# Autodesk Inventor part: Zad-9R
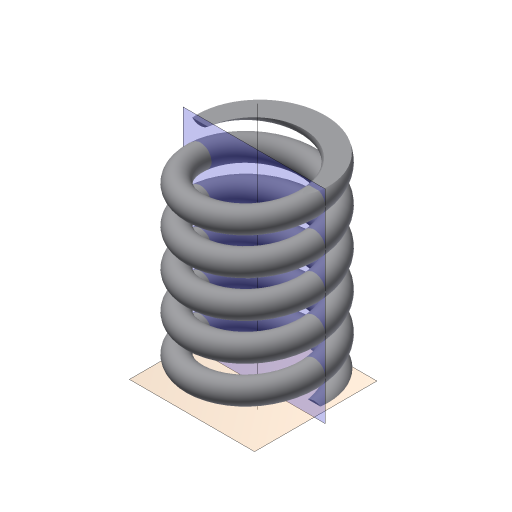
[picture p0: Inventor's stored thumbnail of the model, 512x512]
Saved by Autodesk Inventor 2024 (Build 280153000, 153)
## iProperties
Company: ATC
Shininess: 20.0
Length Units: 11269
Angle Units: 11279
Time Units: 11290
Mass Units: 11283
Length Display Precision: 3
Angle Display Precision: 2
Compacted: True
Created: 2023-03
Part Number: Zad-9R
Document SubType Name: Modeling
Designer: Andrzej Jaskulski
Density: 1 g/cm^3
Material: Default
Appearance: Domyślne
Checked By: A.J.
Engr Approved By: Andrzej Jaskulski
Mfg Approved By: Andrzej Jaskulski
Authority: A.J.
Density: 0.0
Volumn: 0.0
Area: 0.0
PropertySet Name: Model Information
Control State: 0
Master: False
Checked Out: False
Title: A.J.: Kurs R2024-MEP
Author: Andrzej Jaskulski
Revision Number: 1/24
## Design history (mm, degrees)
node "Płaszczyzna1"
node "Płaszczyzna2"
node "Płaszczyzna3"
node "Oś"
feature "Pręt" pitch "d2" = 6.5; turns "d4" = 5.5; dims "d3" = 1, "d5" = 0, angle "d6" = 0 deg, angle "d7" = 0 deg, "d8" = 0, "d9" = 0
  node "Przekrój pręta" dims "d1" = 4
sketch "Prostokąt1"
  geometry: L1 (20, 1.667)-(-34.714, 1.667); L2 (-34.714, 1.667)-(-34.714, -5.488); L3 (-34.714, -5.488)-(20, -5.488); L4 (20, -5.488)-(20, 1.667)
  constraints: 8 end point, 2 horizontal, 2 vertical
extrude "Płaszczyna cięcia dolna" cut sketch "Prostokąt1" stored distance "d10" = 30; taper "d11" = 0 deg
sketch "Prostokąt2"
  geometry: L1 (-29.733, 40.333)-(-29.733, 34.313); L2 (5.799, 40.333)-(-29.733, 40.333); L3 (5.799, 34.313)-(5.799, 40.333); L4 (-29.733, 34.313)-(5.799, 34.313)
  constraints: 8 end point, 2 horizontal, 2 vertical
extrude "Płaszczyna cięcia górna" cut sketch "Prostokąt2" stored distance "d12" = 30; taper "d13" = 0 deg
node "Bryła1"
node "Korpusy bryłowe"
node "Korpusy powierzchniowe"
node "Początek"
sketch "Szkic1"
  geometry: 1 further point
  constraints: 2 other
node "Płaszczyzna YZ"
node "Płaszczyzna XZ"
node "Płaszczyzna XY"
node "Oś X"
node "Oś Y"
node "Oś Z"
node "Początek układu"
other parameters: "d0" = 4 (derived)
